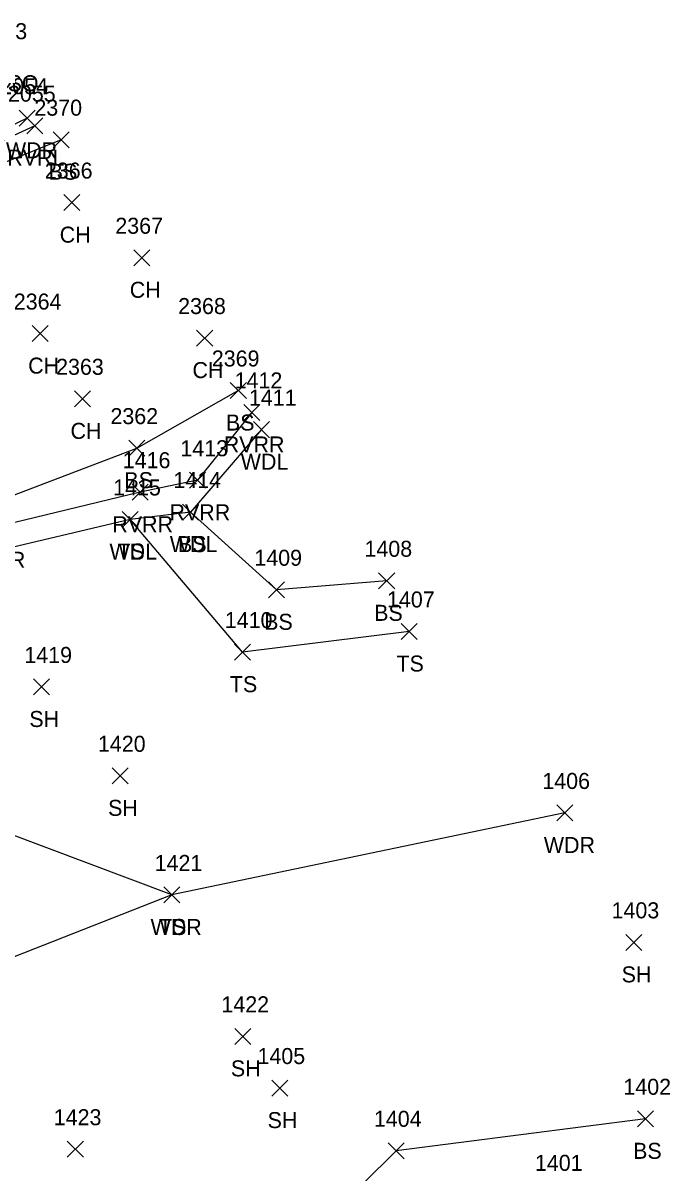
# Model space of a CAD drawing. Extents: x 1501299 to 1502485, y 381423 to 383765.
# Drawn here: x 1501750.2 to 1501831, y 383254.1 to 383397.6 of the extents above; entities that cross this region are included whole.
import ezdxf

# ---------------------------------------------------------------- set-up
doc = ezdxf.new("R2010")
doc.units = 0
for name, color, linetype in [('L_A', 7, 'Continuous'), ('L_C', 7, 'Continuous'), ('L_I', 7, 'Continuous'), ('L_TIC', 7, 'Continuous'), ('LAWA', 7, 'Continuous'), ('LAWE', 7, 'Continuous'), ('LELB', 7, 'Continuous')]:
    doc.layers.add(name, color=color, linetype=linetype)

msp = doc.modelspace()

# ---------------------------------------------------------------- linework, layer by layer
at = {"layer": 'L_TIC'}
for points in [[(1501749.74, 383384.71), (1501751.74, 383386.71)], [(1501751.74, 383384.71), (1501749.74, 383386.71)], [(1501750.7, 383383.78), (1501752.7, 383385.78)], [(1501752.7, 383383.78), (1501750.7, 383385.78)], [(1501754, 383382.03), (1501756, 383384.03)], [(1501756, 383382.03), (1501754, 383384.03)], [(1501755.32, 383374.17), (1501757.32, 383376.17)], [(1501757.32, 383374.17), (1501755.32, 383376.17)], [(1501764.06, 383367.28), (1501766.06, 383369.28)], [(1501766.06, 383367.28), (1501764.06, 383369.28)], [(1501751.39, 383357.81), (1501753.39, 383359.81)], [(1501753.39, 383357.81), (1501751.39, 383359.81)], [(1501771.9, 383357.25), (1501773.9, 383359.25)], [(1501773.9, 383357.25), (1501771.9, 383359.25)], [(1501776.1, 383350.7), (1501778.1, 383352.7)], [(1501778.1, 383350.7), (1501776.1, 383352.7)], [(1501756.67, 383349.66), (1501758.67, 383351.66)], [(1501758.67, 383349.66), (1501756.67, 383351.66)], [(1501777.77, 383347.96), (1501779.77, 383349.96)], [(1501779.77, 383347.96), (1501777.77, 383349.96)], [(1501778.98, 383345.81), (1501780.98, 383347.81)], [(1501780.98, 383345.81), (1501778.98, 383347.81)], [(1501763.44, 383343.5), (1501765.44, 383345.5)], [(1501765.44, 383343.5), (1501763.44, 383345.5)], [(1501770.99, 383339.49), (1501772.99, 383341.49)], [(1501772.99, 383339.49), (1501770.99, 383341.49)], [(1501763.86, 383338), (1501765.86, 383340)], [(1501765.86, 383338), (1501763.86, 383340)], [(1501762.6, 383334.59), (1501764.6, 383336.59)], [(1501764.6, 383334.59), (1501762.6, 383336.59)], [(1501762.6, 383334.59), (1501764.6, 383336.59)], [(1501764.6, 383334.59), (1501762.6, 383336.59)], [(1501770.13, 383335.51), (1501772.13, 383337.51)], [(1501772.13, 383335.51), (1501770.13, 383337.51)], [(1501770.13, 383335.51), (1501772.13, 383337.51)], [(1501772.13, 383335.51), (1501770.13, 383337.51)], [(1501780.88, 383325.81), (1501782.88, 383327.81)], [(1501782.88, 383325.81), (1501780.88, 383327.81)], [(1501794.61, 383326.93), (1501796.61, 383328.93)], [(1501796.61, 383326.93), (1501794.61, 383328.93)], [(1501797.42, 383320.6), (1501799.42, 383322.6)], [(1501799.42, 383320.6), (1501797.42, 383322.6)], [(1501776.63, 383318.02), (1501778.63, 383320.02)], [(1501778.63, 383318.02), (1501776.63, 383320.02)], [(1501751.53, 383313.67), (1501753.53, 383315.67)], [(1501753.53, 383313.67), (1501751.53, 383315.67)], [(1501761.36, 383302.57), (1501763.36, 383304.57)], [(1501763.36, 383302.57), (1501761.36, 383304.57)], [(1501816.85, 383297.93), (1501818.85, 383299.93)], [(1501818.85, 383297.93), (1501816.85, 383299.93)], [(1501767.79, 383287.69), (1501769.79, 383289.69)], [(1501769.79, 383287.69), (1501767.79, 383289.69)], [(1501767.79, 383287.69), (1501769.79, 383289.69)], [(1501769.79, 383287.69), (1501767.79, 383289.69)], [(1501825.44, 383281.77), (1501827.44, 383283.77)], [(1501827.44, 383281.77), (1501825.44, 383283.77)], [(1501776.68, 383270.03), (1501778.68, 383272.03)], [(1501778.68, 383270.03), (1501776.68, 383272.03)], [(1501781.26, 383263.57), (1501783.26, 383265.57)], [(1501783.26, 383263.57), (1501781.26, 383265.57)], [(1501826.92, 383259.73), (1501828.92, 383261.73)], [(1501828.92, 383259.73), (1501826.92, 383261.73)], [(1501755.76, 383255.93), (1501757.76, 383257.93)], [(1501757.76, 383255.93), (1501755.76, 383257.93)], [(1501795.79, 383255.73), (1501797.79, 383257.73)], [(1501797.79, 383255.73), (1501795.79, 383257.73)], [(1501795.79, 383255.73), (1501797.79, 383257.73)], [(1501797.79, 383255.73), (1501795.79, 383257.73)]]:
    msp.add_lwpolyline(points, dxfattribs=at)
at = {"layer": 'LAWA'}
for points in [[(1501750.74, 383385.71), (1501735.53, 383378.38), (1501721.31, 383366.6), (1501707.54, 383358.25), (1501693.27, 383349.98), (1501675.65, 383345.97), (1501663.96, 383338.57), (1501648.34, 383333.74), (1501637.67, 383334.38)], [(1501779.98, 383346.81), (1501771.13, 383336.51), (1501763.6, 383335.59), (1501745.62, 383331.34), (1501736.1, 383321.48), (1501724.6, 383316.37), (1501714.93, 383312.28), (1501706.4, 383305.2), (1501697.06, 383304.74), (1501686.73, 383299.31), (1501680.17, 383293.14), (1501673.64, 383291.8), (1501663.46, 383290.94), (1501650.48, 383288.16), (1501656.05, 383283.21), (1501664.65, 383273.08), (1501676.93, 383259.6)], [(1501817.85, 383298.93), (1501768.79, 383288.69), (1501745.4, 383279.49), (1501730.82, 383289.86), (1501705.12, 383272.32), (1501691.26, 383265.23), (1501684.67, 383261.78), (1501676.93, 383259.6)]]:
    msp.add_lwpolyline(points, dxfattribs=at)
at = {"layer": 'LAWE'}
for points in [[(1501751.7, 383384.78), (1501736.3, 383377.69), (1501721.53, 383363.11), (1501708.28, 383357.65), (1501696.43, 383349.13), (1501679.06, 383342.72), (1501664.77, 383337.17), (1501649.64, 383330.88), (1501644.08, 383325.55), (1501629.2, 383322.95), (1501623.4, 383326.03)], [(1501778.77, 383348.96), (1501771.99, 383340.49), (1501764.86, 383339), (1501746.44, 383334.56), (1501735.81, 383323.47), (1501723.6, 383319.26), (1501713.47, 383313.94), (1501705.44, 383306.76), (1501696, 383307.51), (1501686.23, 383301.86), (1501673.83, 383294.48), (1501662.64, 383293.46), (1501650.05, 383291.22), (1501647.04, 383295.04)]]:
    msp.add_lwpolyline(points, dxfattribs=at)
at = {"layer": 'LELB'}
for points in [[(1501755, 383383.03), (1501740.91, 383377.33), (1501726.44, 383366.41), (1501710.79, 383355.52), (1501696.83, 383347.4), (1501681.96, 383338.63), (1501665.78, 383334.62), (1501652.74, 383328.44), (1501646.39, 383322.76), (1501637.58, 383320.91), (1501629.25, 383319.74), (1501624.75, 383320.37)], [(1501744.21, 383336.81), (1501764.44, 383344.5), (1501777.1, 383351.7)], [(1501795.61, 383327.93), (1501781.88, 383326.81), (1501771.13, 383336.51)], [(1501798.42, 383321.6), (1501777.63, 383319.02), (1501763.6, 383335.59)], [(1501768.79, 383288.69), (1501732.35, 383302.39), (1501714.93, 383312.28)], [(1501827.92, 383260.73), (1501796.79, 383256.73)], [(1501744.07, 383157.49), (1501739.64, 383178.69), (1501749.13, 383198.43), (1501757.23, 383209.84), (1501762.68, 383226.96), (1501780.07, 383240.14), (1501796.79, 383256.73)]]:
    msp.add_lwpolyline(points, dxfattribs=at)

# ---------------------------------------------------------------- texts
at = {"layer": 'L_A'}
for s, p in [('WDR', (1501748.1, 383380.71)), ('RVRL', (1501748.27, 383379.78)), ('BS', (1501753.44, 383378.03)), ('CH', (1501754.81, 383370.17)), ('CH', (1501763.55, 383363.28)), ('CH', (1501750.88, 383353.81)), ('CH', (1501771.38, 383353.25)), ('BS', (1501775.55, 383346.7)), ('CH', (1501756.16, 383345.66)), ('RVRR', (1501775.28, 383343.96)), ('WDL', (1501777.4, 383341.81)), ('BS', (1501762.88, 383339.5)), ('RVRR', (1501768.51, 383335.49)), ('RVRR', (1501761.37, 383334)), ('WDL', (1501768.55, 383331.51)), ('BS', (1501769.57, 383331.51)), ('WDL', (1501761.02, 383330.59)), ('TS', (1501762.01, 383330.59)), ('RVRR', (1501742.95, 383329.56)), ('BS', (1501794.05, 383322.93)), ('BS', (1501780.32, 383321.81)), ('TS', (1501796.83, 383316.6)), ('TS', (1501776.04, 383314.02)), ('SH', (1501751.02, 383309.67)), ('SH', (1501760.85, 383298.57)), ('WDR', (1501815.22, 383293.93)), ('WDR', (1501766.15, 383283.69)), ('TS', (1501767.19, 383283.69)), ('SH', (1501824.93, 383277.77)), ('SH', (1501776.17, 383266.03)), ('SH', (1501780.75, 383259.57)), ('BS', (1501826.36, 383255.73))]:
    msp.add_text(s, height=2, dxfattribs=at).set_placement(p)
at = {"layer": 'L_C'}
msp.add_text('W/FNBW ALSO', height=2, dxfattribs=at).set_placement((1501733.15, 383389.08))
at = {"layer": 'L_I'}
for s, p in [('2053', (1501744.8, 383395.58)), ('2054', (1501747.4, 383388.71)), ('2055', (1501748.36, 383387.78)), ('2370', (1501751.65, 383386.03)), ('2366', (1501752.96, 383378.17)), ('2367', (1501761.75, 383371.28)), ('2364', (1501749.08, 383361.81)), ('2368', (1501769.59, 383361.25)), ('2369', (1501773.79, 383354.7)), ('2363', (1501754.36, 383353.66)), ('1412', (1501776.64, 383351.96)), ('1411', (1501778.42, 383349.81)), ('2362', (1501761.14, 383347.5)), ('1413', (1501769.87, 383343.49)), ('1416', (1501762.68, 383342)), ('1415', (1501761.48, 383338.59)), ('1415', (1501761.48, 383338.59)), ('1414', (1501769, 383339.51)), ('1414', (1501769, 383339.51)), ('1408', (1501792.84, 383330.93)), ('1409', (1501779.1, 383329.81)), ('1407', (1501795.65, 383324.6)), ('1410', (1501775.41, 383322.02)), ('1419', (1501750.4, 383317.67)), ('1420', (1501759.58, 383306.57)), ('1406', (1501815.03, 383301.93)), ('1421', (1501766.66, 383291.69)), ('1421', (1501766.66, 383291.69)), ('1403', (1501823.67, 383285.77)), ('1422', (1501774.99, 383274.03)), ('1405', (1501779.49, 383267.57)), ('1402', (1501825.15, 383263.73)), ('1423', (1501754.07, 383259.93)), ('1404', (1501794.02, 383259.73)), ('1404', (1501794.02, 383259.73)), ('1401', (1501814.11, 383254.23))]:
    msp.add_text(s, height=2, dxfattribs=at).set_placement(p)

doc.saveas('drawing.dxf')
